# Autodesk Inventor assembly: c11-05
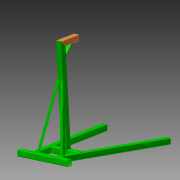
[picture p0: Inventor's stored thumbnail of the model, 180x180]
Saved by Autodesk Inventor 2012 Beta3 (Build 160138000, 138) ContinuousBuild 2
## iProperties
Created: 2011-01
Part Number: c11-05
Document SubType Name: Assembly
Designer: Beta-8540w
_SolveAssemblyDoc: Frame Generator Solve Assembly
_Version: 15.0.0
Author: Beta-8540w
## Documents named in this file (3)
- C:\Inventor 2012 Essentials\Assemblies\Chapter 11\c11-05.iam
- C:\Inventor 2012 Essentials\Parts\Chapter 11\c11-01.ipt
- C:\Inventor 2012 Essentials\Assemblies\Chapter 11\Frame\Frame c11-05.iam
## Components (2 placed, 2 different names)
1. c11-01:1
2. Frame c11-05:1 [sub-assembly]
